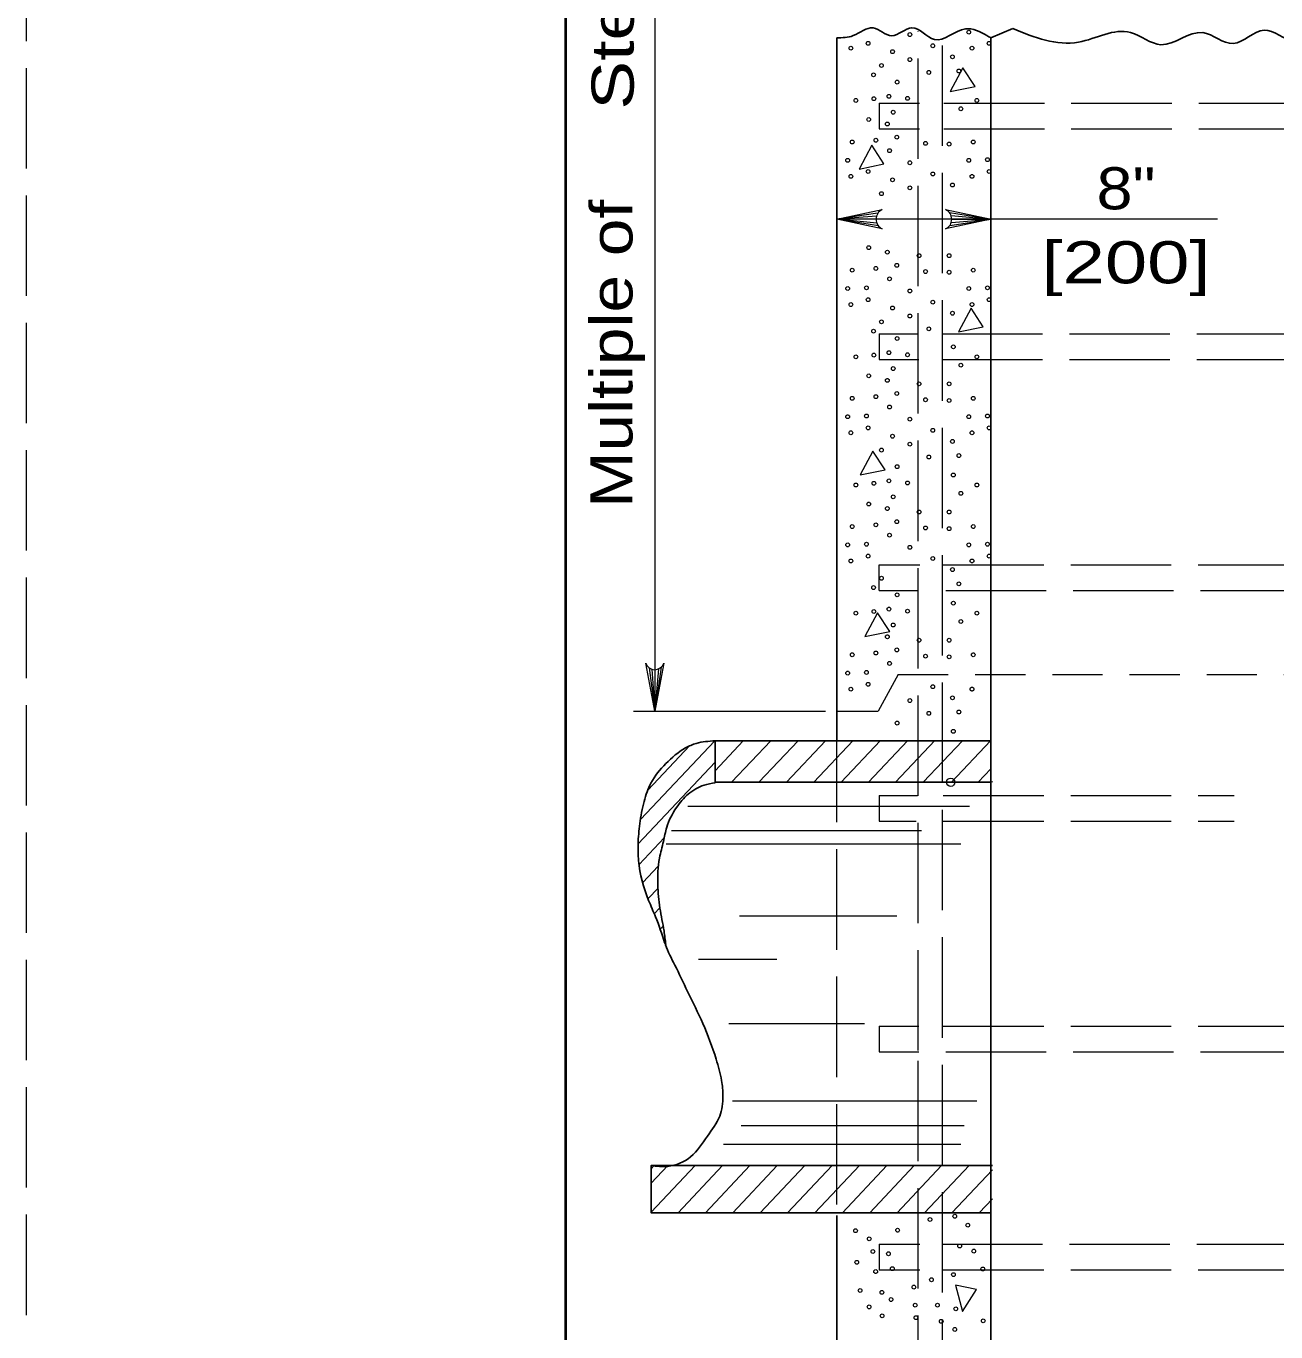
# Model space of a CAD drawing. Extents: x 1329.9 to 1363.9, y 715.5 to 737.5.
# Drawn here: x 1329.863 to 1334.495, y 723.847 to 728.685 of the extents above; entities that cross this region are included whole.
import ezdxf
from ezdxf.enums import TextEntityAlignment as Align

# ---------------------------------------------------------------- set-up
doc = ezdxf.new("R2010")
doc.units = 0
doc.header["$LTSCALE"] = 0.062
doc.header["$PDMODE"] = 32
doc.header["$PDSIZE"] = 0.031
doc.linetypes.add('LONG_DASHED', pattern=[7.5, 6, -1.5])
doc.linetypes.add('MEDIUM_DASHED', pattern=[4.5, 3, -1.5])
doc.layers.add('1', color=7, linetype='Continuous', lineweight=13)

msp = doc.modelspace()

# ---------------------------------------------------------------- linework, layer by layer
at = {"layer": '1', "linetype": 'LONG_DASHED'}
for p, q in [((1333.16925, 724.889), (1333.16925, 728.6655)), ((1333.259, 722.105), (1333.259, 728.643)), ((1333.02425, 728.39908), (1333.02425, 728.30408)), ((1333.02425, 728.39908), (1333.17375, 728.39908)), ((1333.26492, 728.39908), (1338.06333, 728.39908)), ((1333.02425, 728.30408), (1333.17375, 728.30408)), ((1333.26492, 728.30408), (1338.07692, 728.30408)), ((1333.02425, 727.54417), (1333.02425, 727.44925)), ((1333.02425, 727.54417), (1333.16692, 727.54417)), ((1333.258, 727.54417), (1338.08825, 727.54417)), ((1333.02425, 727.44925), (1333.17142, 727.44925)), ((1333.258, 727.44925), (1338.08367, 727.44925)), ((1333.02425, 726.59433), (1333.02425, 726.68933)), ((1333.02425, 726.68933), (1333.176, 726.68933)), ((1333.26258, 726.68933), (1338.07467, 726.68933)), ((1333.02425, 726.59433), (1333.16933, 726.59433)), ((1333.27167, 726.59433), (1338.07917, 726.59433)), ((1332.86792, 724.31917), (1332.86792, 726.0445)), ((1333.02425, 725.8345), (1333.02425, 725.7395)), ((1333.02425, 725.8345), (1333.16692, 725.8345)), ((1333.26258, 725.8345), (1334.341, 725.8345)), ((1333.02425, 725.7395), (1333.16233, 725.7395)), ((1333.26258, 725.7395), (1334.341, 725.7395)), ((1333.02425, 724.97958), (1333.02425, 724.88458)), ((1333.02425, 724.97958), (1333.17142, 724.97958)), ((1333.26258, 724.97958), (1338.07917, 724.97958)), ((1333.02425, 724.88458), (1333.17142, 724.88458)), ((1333.16925, 722.11933), (1333.16925, 724.87933)), ((1333.27167, 724.88458), (1338.07467, 724.88458)), ((1333.02425, 724.1725), (1333.02425, 724.0775)), ((1333.02425, 724.1725), (1333.176, 724.1725)), ((1333.258, 724.1725), (1338.08367, 724.1725)), ((1333.02425, 724.0775), (1333.176, 724.0775)), ((1333.26258, 724.0775), (1338.07467, 724.0775))]:
    msp.add_line(p, q, dxfattribs=at)
at = {"layer": '1', "lineweight": 25}
for p, q in [((1333.43842, 728.6415), (1333.52008, 728.67558)), ((1332.86792, 726.03683), (1332.86792, 728.6415)), ((1333.43842, 728.6415), (1333.43842, 726.04008)), ((1332.417, 725.88342), (1332.417, 726.03892)), ((1333.43842, 726.04008), (1333.43842, 720.98492)), ((1332.14017, 725.74492), (1332.41583, 726.03675)), ((1332.417, 726.03383), (1332.41983, 726.03683)), ((1332.86792, 726.03683), (1332.417, 726.03683)), ((1333.43842, 726.03683), (1332.86792, 726.03683)), ((1332.86792, 718.46475), (1332.86792, 724.27833))]:
    msp.add_line(p, q, dxfattribs=at)
at = {"layer": '1'}
for p, q in [((1333.02017, 727.99175), (1332.86792, 727.96925)), ((1333.015, 727.98058), (1332.86792, 727.96925)), ((1333.28533, 727.99417), (1333.43942, 727.96925)), ((1333.29117, 727.98375), (1333.43942, 727.96925)), ((1333.0135, 727.96925), (1332.86792, 727.96925)), ((1333.01617, 727.95475), (1332.86792, 727.96925)), ((1333.022, 727.94425), (1332.86792, 727.96925)), ((1334.2785, 727.96925), (1332.86792, 727.96925)), ((1333.43942, 727.96925), (1333.23725, 727.96925)), ((1333.28708, 727.94667), (1333.43942, 727.96925)), ((1333.29225, 727.95783), (1333.43942, 727.96925)), ((1333.29383, 727.96925), (1333.43942, 727.96925)), ((1332.17183, 726.30767), (1332.19317, 726.14642)), ((1332.18242, 726.30217), (1332.19317, 726.14642)), ((1332.21667, 726.30958), (1332.19317, 726.14642)), ((1332.20683, 726.30342), (1332.19317, 726.14642)), ((1332.19317, 726.3005), (1332.19317, 726.14642)), ((1332.11442, 726.14642), (1332.82617, 726.14642)), ((1333.08583, 725.88425), (1333.23075, 726.03767)), ((1332.16725, 725.85425), (1332.32333, 726.01942)), ((1332.417, 725.92633), (1332.52133, 726.03683)), ((1332.47792, 725.88342), (1332.62283, 726.03683)), ((1332.57942, 725.88342), (1332.72433, 726.03683)), ((1332.68092, 725.88342), (1332.82592, 726.03683)), ((1332.78233, 725.88342), (1332.92733, 726.03675)), ((1332.88392, 725.88342), (1333.02883, 726.03675)), ((1332.98542, 725.88342), (1333.13033, 726.03675)), ((1333.18842, 725.88342), (1333.33333, 726.03675)), ((1333.29267, 725.88342), (1333.4375, 726.03675)), ((1332.1315, 725.65508), (1332.417, 725.95742)), ((1333.39142, 725.88342), (1333.43817, 725.93283)), ((1333.44217, 725.88342), (1333.44475, 725.88608)), ((1332.31517, 725.79517), (1333.35992, 725.79517)), ((1332.25567, 725.70408), (1333.18142, 725.70408)), ((1332.13575, 725.579), (1332.22825, 725.67692)), ((1332.23583, 725.65508), (1333.32692, 725.65508)), ((1332.149, 725.5125), (1332.20583, 725.57267)), ((1332.16825, 725.45233), (1332.20517, 725.49133)), ((1332.19142, 725.39625), (1332.21225, 725.41833)), ((1332.50742, 725.38908), (1333.09067, 725.38908)), ((1332.21233, 725.33783), (1332.22417, 725.35025)), ((1332.35483, 725.22808), (1332.64575, 725.22808)), ((1332.46725, 724.99008), (1332.96983, 724.99008)), ((1332.48092, 724.703), (1333.38642, 724.703)), ((1332.5135, 724.612), (1333.34008, 724.612)), ((1332.44742, 724.542), (1333.32692, 724.542)), ((1332.1795, 724.29025), (1332.34275, 724.46308)), ((1332.1795, 724.39775), (1332.24125, 724.46308)), ((1332.1795, 724.4515), (1332.1905, 724.46308)), ((1332.27933, 724.28858), (1332.44425, 724.46308)), ((1332.38092, 724.28858), (1332.54575, 724.46308)), ((1332.48233, 724.28858), (1332.64725, 724.46308)), ((1332.58392, 724.28867), (1332.74875, 724.46308)), ((1332.68542, 724.28867), (1332.85025, 724.46308)), ((1332.78692, 724.28867), (1332.95175, 724.46308)), ((1332.8885, 724.28867), (1333.05325, 724.46308)), ((1332.98992, 724.28858), (1333.15467, 724.46308)), ((1333.09133, 724.28858), (1333.25625, 724.46308)), ((1333.19292, 724.28858), (1333.35775, 724.46308)), ((1333.29442, 724.28858), (1333.44475, 724.44767)), ((1333.39592, 724.28858), (1333.44475, 724.34025))]:
    msp.add_line(p, q, dxfattribs=at)
at = {"layer": '1', "linetype": 'MEDIUM_DASHED'}
for p in [(1333.095, 726.28267), (1332.86717, 726.14642)]:
    msp.add_line(p, (1333.02075, 726.14642), dxfattribs=at)
at = {"layer": '1', "linetype": 'LONG_DASHED'}
msp.add_lwpolyline([(1329.86333, 715.4975), (1363.86333, 715.4975), (1363.86333, 737.4975), (1329.86333, 737.4975)], close=True, dxfattribs=at)
at = {"layer": '1', "lineweight": 25}
for points in [[(1363.36333, 715.9975), (1331.86333, 715.9975), (1331.86333, 736.9975)], [(1332.417, 726.03892), (1332.417, 725.88342), (1333.43842, 725.88342)], [(1333.44475, 724.46308), (1332.1795, 724.46308), (1332.1795, 724.28858), (1332.5875, 724.28858), (1333.43842, 724.28858)]]:
    msp.add_lwpolyline(points, dxfattribs=at)
at = {"layer": '1', "lineweight": 40}
msp.add_lwpolyline([(1331.86333, 736.9975), (1363.36333, 736.9975), (1363.36333, 715.9975), (1331.86333, 715.9975)], close=True, dxfattribs=at)
msp.add_lwpolyline([(1331.86333, 736.9975), (1363.36333, 736.9975), (1363.36333, 715.9975), (1331.86333, 715.9975)], close=True, dxfattribs=at)
at = {"layer": '1'}
for points in [[(1332.19317, 733.47708), (1332.19317, 730.587), (1332.19317, 726.14642)], [(1333.03608, 727.93358), (1332.86792, 727.96925), (1333.03608, 728.00483)], [(1333.27117, 728.00483), (1333.43942, 727.96925), (1333.27117, 727.93358)], [(1332.22683, 726.3245), (1332.19317, 726.14642), (1332.1595, 726.3245)]]:
    msp.add_lwpolyline(points, dxfattribs=at)
for points in [[(1333.33525, 728.53008), (1333.28842, 728.44208), (1333.38017, 728.461)], [(1332.99725, 728.24325), (1332.95033, 728.15525), (1333.04217, 728.17425)], [(1333.36558, 727.63983), (1333.31875, 727.55183), (1333.41058, 727.57083)], [(1333.0015, 727.10983), (1332.95467, 727.02175), (1333.04642, 727.04075)], [(1333.01883, 726.51108), (1332.972, 726.42308), (1333.06375, 726.44208)], [(1333.30758, 724.01975), (1333.33325, 723.92242), (1333.3855, 724.00467)]]:
    msp.add_lwpolyline(points, close=True, dxfattribs=at)
at = {"layer": '1', "linetype": 'MEDIUM_DASHED'}
msp.add_lwpolyline([(1333.095, 726.28267), (1338.24792, 726.28267), (1338.32433, 726.14242), (1338.45892, 726.14242)], dxfattribs=at)
at = {"layer": '1'}
for centre in [(1333.13859, 728.65343), (1333.35667, 728.66245), (1332.9202, 728.60301), (1332.9836, 728.62097), (1333.22344, 728.61203), (1333.36879, 728.60301), (1333.43219, 728.62097), (1333.07444, 728.59018), (1333.13859, 728.56074), (1333.29612, 728.57095), (1333.00416, 728.5043), (1333.03324, 728.53889), (1333.20887, 728.51324), (1333.32034, 728.51839), (1333.09141, 728.47731), (1332.93837, 728.40939), (1333.00536, 728.41581), (1333.06113, 728.42475), (1333.13014, 728.41707), (1333.38695, 728.40939), (1333.07683, 728.36578), (1333.32759, 728.3786), (1332.98599, 728.33887), (1333.05507, 728.32217), (1333.01261, 728.26193), (1333.09014, 728.27341), (1332.92506, 728.25552), (1333.06352, 728.22346), (1333.19675, 728.25037), (1333.284, 728.24776), (1333.37365, 728.25552), (1332.90809, 728.18752), (1333.13859, 728.1785), (1333.35667, 728.18752), (1333.42613, 728.19006), (1332.9202, 728.12808), (1332.9836, 728.14605), (1333.07444, 728.11526), (1333.22344, 728.1371), (1333.36879, 728.12808), (1333.43219, 728.14605), (1333.03324, 728.06397), (1333.13859, 728.08581), (1333.29612, 728.09602), (1332.98599, 727.86394), (1333.05507, 727.84724), (1333.17253, 727.83442), (1333.284, 727.83442), (1332.92506, 727.78059), (1333.01261, 727.787), (1333.09014, 727.79848), (1333.19675, 727.77545), (1333.284, 727.77284), (1333.37365, 727.78059), (1333.06352, 727.74854), (1332.90809, 727.7126), (1332.97754, 727.71513), (1333.13859, 727.70358), (1333.35667, 727.7126), (1333.42613, 727.71513), (1332.9202, 727.65315), (1332.9836, 727.67112), (1333.07444, 727.64033), (1333.22344, 727.66218), (1333.36879, 727.65315), (1333.43219, 727.67112), (1333.03324, 727.58904), (1333.13859, 727.61089), (1333.29612, 727.6211), (1333.00416, 727.55445), (1333.20887, 727.56339), (1333.09141, 727.52746), (1333.2997, 727.49675), (1332.93837, 727.45954), (1333.00536, 727.46596), (1333.06113, 727.4749), (1333.13014, 727.46722), (1333.38695, 727.45954), (1332.98599, 727.38902), (1333.07683, 727.41593), (1333.32759, 727.42875), (1333.05507, 727.37232), (1333.17253, 727.35949), (1333.284, 727.35949), (1332.92506, 727.30567), (1333.01261, 727.31208), (1333.09014, 727.32356), (1333.19675, 727.30052), (1333.284, 727.29791), (1333.37365, 727.30567), (1332.97754, 727.24021), (1333.06352, 727.27361), (1333.42613, 727.24021), (1332.90809, 727.23767), (1332.9836, 727.1962), (1333.13859, 727.22865), (1333.35667, 727.23767), (1333.43219, 727.1962), (1332.9202, 727.17823), (1333.07444, 727.16541), (1333.22344, 727.18725), (1333.29612, 727.14617), (1333.36879, 727.17823), (1333.03324, 727.11411), (1333.13859, 727.13596), (1333.09141, 727.05253), (1333.20887, 727.08847), (1333.32034, 727.09361), (1333.06113, 726.99997), (1333.2997, 727.02182), (1332.93837, 726.98462), (1333.00536, 726.99103), (1333.13014, 726.9923), (1333.32759, 726.95383), (1333.38695, 726.98462), (1332.98599, 726.91409), (1333.07683, 726.941), (1333.05507, 726.89739), (1333.17253, 726.88457), (1333.284, 726.88457), (1332.92506, 726.83074), (1333.01261, 726.83715), (1333.09014, 726.84863), (1333.19675, 726.8256), (1333.284, 726.82299), (1333.37365, 726.83074), (1332.90809, 726.76275), (1332.97754, 726.76528), (1333.06352, 726.79869), (1333.35667, 726.76275), (1333.42613, 726.76528), (1332.9836, 726.72127), (1333.13859, 726.75373), (1333.22344, 726.71233), (1333.43219, 726.72127), (1332.9202, 726.7033), (1333.29612, 726.67125), (1333.36879, 726.7033), (1333.03324, 726.63919), (1333.32034, 726.61869), (1333.00416, 726.6046), (1333.09141, 726.57761), (1333.00536, 726.5161), (1333.06113, 726.52505), (1333.13014, 726.51737), (1333.2997, 726.5469), (1332.93837, 726.50969), (1333.07683, 726.46608), (1333.32759, 726.4789), (1333.38695, 726.50969), (1333.05507, 726.42247), (1333.09014, 726.37371), (1333.17253, 726.40964), (1333.284, 726.40964), (1332.92506, 726.35582), (1333.01261, 726.36223), (1333.06352, 726.32376), (1333.19675, 726.35067), (1333.284, 726.34806), (1333.37365, 726.35582), (1332.90809, 726.28782), (1332.97754, 726.29036), (1332.9202, 726.22838), (1332.9836, 726.24635), (1333.22344, 726.2374), (1333.13859, 726.18611), (1333.29612, 726.19632), (1333.20887, 726.13862), (1333.32034, 726.14376), (1333.09141, 726.10268), (1333.2997, 726.07197), (1333.21321, 724.26365), (1333.30482, 724.27546), (1333.35309, 724.2425), (1332.9374, 724.22195), (1333.09325, 724.22375), (1332.98789, 724.19201), (1333.00163, 724.14488), (1333.32312, 724.16542), (1333.37535, 724.14639), (1332.94163, 724.10498), (1333.05899, 724.13666), (1333.01184, 724.0705), (1333.07353, 724.08141), (1333.29996, 724.0593), (1333.40871, 724.08018), (1332.95421, 724.00042), (1333.15352, 724.01307), (1333.21855, 724.04027), (1333.03505, 723.99343), (1333.06872, 723.96684), (1332.98762, 723.93964), (1333.03589, 723.90667), (1333.15865, 723.94596), (1333.24091, 723.94596), (1333.30852, 723.93236), (1333.16118, 723.89973), (1333.2546, 723.88613), (1333.30509, 723.85619), (1333.41045, 723.88792)]:
    msp.add_ellipse(centre, major_axis=(0, 0.00718), ratio=0.944544, dxfattribs=at)
for centre, major_axis, start_param, end_param in [((1333.04977, 727.96922), (0, 0.03844), 0.3855052, 2.7561184), ((1333.25753, 727.96922), (0, -0.03844), 0.3855052, 2.7561184), ((1332.19315, 726.33897), (0, -0.03844), 5.0978942, 7.4685073)]:
    msp.add_ellipse(centre, major_axis=major_axis, ratio=0.944544, start_param=start_param, end_param=end_param, dxfattribs=at)
at = {"layer": '1', "linetype": 'LONG_DASHED'}
msp.add_ellipse((1333.36879, 726.22838), major_axis=(0, 0.00718), ratio=0.944544, dxfattribs=at)
at = {"layer": '1', "lineweight": 25}
for points in [[(1332.86792, 728.6415), (1332.92858, 728.64942), (1333.00225, 728.678), (1333.07117, 728.64908), (1333.14583, 728.67867), (1333.22958, 728.63517), (1333.34433, 728.67467), (1333.42442, 728.64967), (1333.43842, 728.6415)], [(1333.52008, 728.67558), (1333.764, 728.62533), (1333.95642, 728.66133), (1334.06917, 728.616), (1334.22383, 728.66058), (1334.33658, 728.62017), (1334.45125, 728.66942), (1334.564, 728.63092), (1334.66558, 728.65867), (1334.77825, 728.627), (1334.88925, 728.64892), (1334.99642, 728.62208), (1335.10917, 728.66942), (1335.25733, 728.62725), (1335.385, 728.661), (1335.4865, 728.62633), (1335.67392, 728.6535), (1335.81275, 728.6405), (1335.91158, 728.65942), (1336.02233, 728.62), (1336.13892, 728.6585), (1336.26842, 728.62108), (1336.45208, 728.64333), (1336.56475, 728.62433), (1336.71575, 728.65042), (1336.80425, 728.60692), (1336.95433, 728.6515), (1337.08383, 728.60817), (1337.19208, 728.64558)], [(1332.417, 726.03683), (1332.34608, 726.02725), (1332.30742, 726.01092), (1332.23417, 725.9525), (1332.17883, 725.88058), (1332.15383, 725.81258), (1332.13767, 725.73017), (1332.13142, 725.65433), (1332.13308, 725.593), (1332.17042, 725.44525), (1332.19625, 725.38483), (1332.22958, 725.29017)], [(1332.23417, 725.28258), (1332.2275, 725.332), (1332.21233, 725.41742), (1332.20433, 725.50367), (1332.21075, 725.6025), (1332.22508, 725.66383), (1332.23758, 725.71658), (1332.27333, 725.78942), (1332.317, 725.83925), (1332.37592, 725.87275), (1332.417, 725.88133)], [(1332.22958, 725.29017), (1332.23275, 725.28117), (1332.2675, 725.20633), (1332.31467, 725.1085), (1332.37158, 724.9895), (1332.42058, 724.858), (1332.441, 724.77842), (1332.44542, 724.72083), (1332.43375, 724.64608), (1332.38825, 724.57225), (1332.32575, 724.49558), (1332.241, 724.46017), (1332.1795, 724.46308)]]:
    msp.add_spline(points, degree=3, dxfattribs=at)
at = {"layer": '1'}
msp.add_point((1333.28992, 725.88342), dxfattribs=at)

# ---------------------------------------------------------------- texts
for s, width, p in [('Step Spacing', 1.3, (1332.11508, 728.37517)), ('Multiple of', 1.2, (1332.11042, 726.90025))]:
    msp.add_text(s, height=0.156, rotation=90, dxfattribs=dict(at, width=width)).set_placement(p)
for s, width, p in [('8"', 1.15, (1333.93967, 728.00592)), ('[200]', 1.35, (1333.93967, 727.73183))]:
    msp.add_text(s, height=0.156, dxfattribs=dict(at, width=width)).set_placement(p, align=Align.CENTER)

doc.saveas('drawing.dxf')
